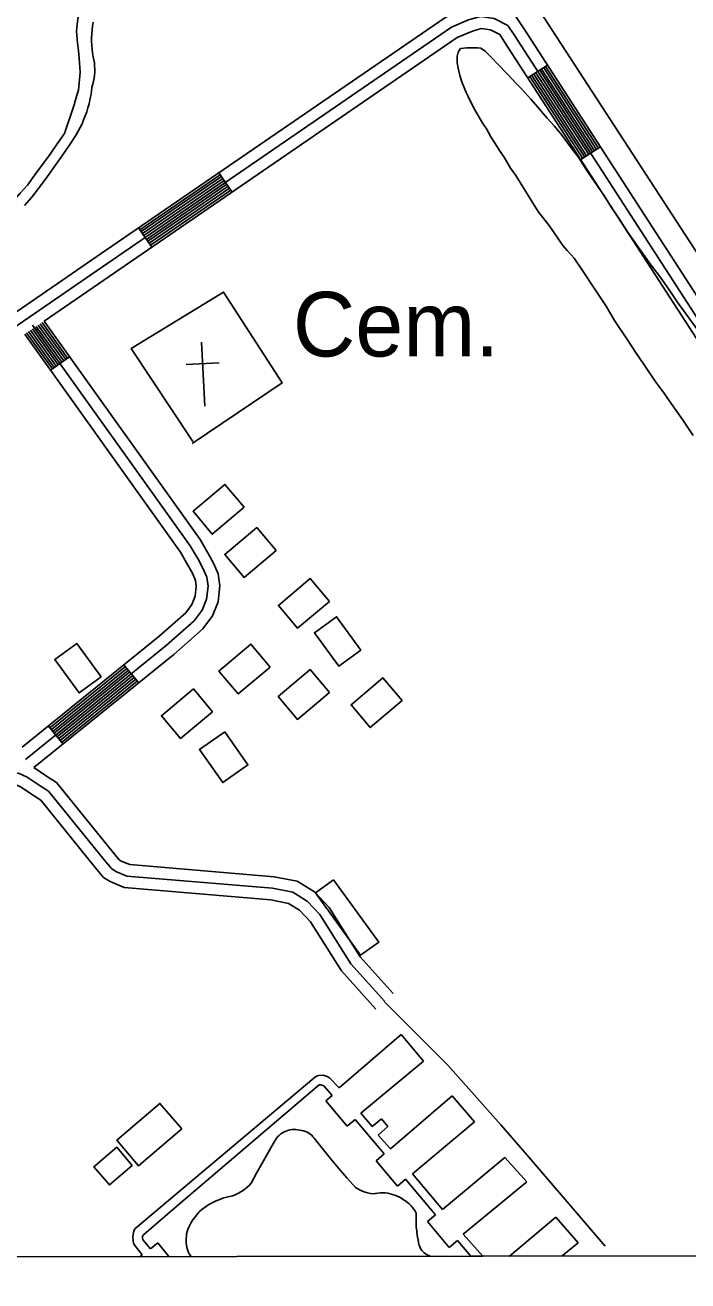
# Model space of a CAD drawing. Extents: x 3324104 to 3361979, y 612876 to 638273.
# Drawn here: x 3345889 to 3346740, y 618257 to 619871 of the extents above; entities that cross this region are included whole.
import ezdxf

# ---------------------------------------------------------------- set-up
doc = ezdxf.new("R2010")
doc.units = 0
for name, color, linetype in [('V-BLDG-OTLN', 7, 'Continuous'), ('V-GRID-FRAM', 7, 'Continuous'), ('V-ROAD-CNTR', 7, 'Continuous'), ('V-SITE-OTLN', 7, 'Continuous'), ('V-SITE-OTLN-IDEN', 7, 'Continuous'), ('V-SITE-VEGE', 7, 'Continuous'), ('V-TOPO-SHOR', 7, 'Continuous')]:
    doc.layers.add(name, color=color, linetype=linetype)

msp = doc.modelspace()

# ---------------------------------------------------------------- linework, layer by layer
at = {"layer": 'V-BLDG-OTLN'}
for p, q in [((3346292.4, 618504.9), (3346372.1, 618573.4)), ((3346372.1, 618573.4), (3346400.5, 618539.2)), ((3346400.5, 618539.2), (3346320.3, 618472.3)), ((3346029.9, 618323.9), (3346259.8, 618517.6)), ((3346259.8, 618517.6), (3346263.1, 618520)), ((3346263.1, 618520), (3346264.4, 618520.4)), ((3346266.8, 618508.8), (3346263.9, 618506.8)), ((3346264.4, 618520.4), (3346266.1, 618520.8)), ((3346266.1, 618520.8), (3346271.9, 618521.2)), ((3346268.9, 618508.8), (3346266.8, 618508.8)), ((3346272.8, 618507.5), (3346268.9, 618508.8)), ((3346271.9, 618521.2), (3346273.1, 618520.8)), ((3346273.1, 618520.8), (3346276.8, 618519.5)), ((3346276.8, 618519.5), (3346279.7, 618517.8)), ((3346279.7, 618517.8), (3346292.4, 618504.9)), ((3346263.9, 618506.8), (3346081.1, 618350.8)), ((3346283.2, 618495.2), (3346272.8, 618507.5)), ((3346275.1, 618488.4), (3346283.2, 618495.2)), ((3346358.1, 618426.8), (3346437.4, 618494.6)), ((3346437.4, 618494.6), (3346466.1, 618461.2)), ((3346302.6, 618455.7), (3346275.1, 618488.4)), ((3346312.8, 618464.3), (3346302.6, 618455.7)), ((3346350.1, 618420), (3346312.8, 618464.3)), ((3346320.3, 618472.3), (3346334.7, 618455.2)), ((3346334.7, 618455.2), (3346346.8, 618465.1)), ((3346346.8, 618465.1), (3346355, 618455.5)), ((3346466.1, 618461.2), (3346386.4, 618394.7)), ((3346355, 618455.5), (3346342.5, 618444.4)), ((3346342.5, 618444.4), (3346358.1, 618426.8)), ((3346339.7, 618411.2), (3346350.1, 618420)), ((3346425, 618348.8), (3346505.1, 618415.7)), ((3346505.1, 618415.7), (3346533.4, 618384.4)), ((3346367.1, 618378.7), (3346339.7, 618411.2)), ((3346377.7, 618387.6), (3346367.1, 618378.7)), ((3346416.1, 618342), (3346377.7, 618387.6)), ((3346386.4, 618394.7), (3346425, 618348.8)), ((3346533.4, 618384.4), (3346451.7, 618317.1)), ((3346081.1, 618350.8), (3346041, 618316.3)), ((3346405.6, 618333.2), (3346416.1, 618342)), ((3346433.7, 618299.8), (3346405.6, 618333.2)), ((3346511.1, 618288.9), (3346570.8, 618338.9)), ((3346570.8, 618338.9), (3346599.5, 618305.9)), ((3346027.3, 618313.9), (3346027.8, 618316.4)), ((3346027.8, 618316.4), (3346028.6, 618321)), ((3346028.6, 618321), (3346029.9, 618323.9)), ((3346041, 618316.3), (3346039.8, 618314.3)), ((3346451.7, 618317.1), (3346476.9, 618288.8)), ((3346027.7, 618308.1), (3346027.3, 618313.9)), ((3346028.5, 618304), (3346027.7, 618308.1)), ((3346039.2, 618290.6), (3346028.5, 618304)), ((3346039.8, 618314.3), (3346039.8, 618312.2)), ((3346039.8, 618312.2), (3346040.1, 618309.7)), ((3346040.1, 618309.7), (3346050, 618298)), ((3346050, 618298), (3346059.2, 618305.8)), ((3346059.2, 618305.8), (3346073.5, 618288.1)), ((3346444.4, 618308.8), (3346433.7, 618299.8)), ((3346461.3, 618288.8), (3346444.4, 618308.8)), ((3346599.5, 618305.9), (3346578.9, 618289)), ((3346036.2, 618288), (3346039.2, 618290.6)), ((3346073.5, 618288.1), (3346036.2, 618288)), ((3346476.9, 618288.8), (3346461.3, 618288.8)), ((3346578.9, 618289), (3346511.1, 618288.9))]:
    msp.add_line(p, q, dxfattribs=at)
for points in [[(3346170.3, 619251.1), (3346129.3, 619216.5), (3346104.6, 619245.9), (3346145.6, 619280.4)], [(3346211.2, 619195.6), (3346170.2, 619161), (3346145.4, 619190.4), (3346186.4, 619224.9)], [(3346280, 619130.2), (3346239, 619095.6), (3346214.3, 619125), (3346255.2, 619159.5)], [(3346320.2, 619067.6), (3346289, 619110.5), (3346260.6, 619089.9), (3346291.8, 619047)], [(3345986.6, 619033.2), (3345955.4, 619076.1), (3345927, 619055.5), (3345958.2, 619012.5)], [(3346203.7, 619045.8), (3346162.7, 619011.3), (3346137.9, 619040.6), (3346178.9, 619075.2)], [(3346279.7, 619013), (3346238.7, 618978.5), (3346214, 619007.8), (3346255, 619042.4)], [(3346373.3, 619002.6), (3346332.3, 618968), (3346307.6, 618997.4), (3346348.6, 619031.9)], [(3346129.7, 618988.3), (3346088.7, 618953.8), (3346064, 618983.1), (3346105, 619017.7)], [(3346145.3, 618962.4), (3346175.2, 618920.1), (3346142.8, 618897.2), (3346112.9, 618939.6)], [(3346285, 618772.2), (3346343.1, 618692.1), (3346319.9, 618675.3), (3346261.8, 618755.4)], [(3346090.1, 618452.3), (3346034.7, 618404.9), (3346006.7, 618437.7), (3346062.1, 618485)], [(3346026.5, 618405.3), (3345997.1, 618380.3), (3345977.3, 618403.7), (3346006.8, 618428.6)]]:
    msp.add_lwpolyline(points, close=True, dxfattribs=at)
at = {"layer": 'V-GRID-FRAM'}
msp.add_lwpolyline([(3328194.1, 636440.7), (3359767.9, 636495.9), (3359807.6, 618312.1), (3328217.9, 618256.9), (3328194.1, 636440.7)], dxfattribs=at)
at = {"layer": 'V-ROAD-CNTR'}
for p, q in [((3346560, 619819.2), (3346534.8, 619802.9)), ((3346627.9, 619714.2), (3346602.7, 619697.9)), ((3346137.8, 619681), (3346154.7, 619656.2)), ((3346034.7, 619610.2), (3346051.7, 619585.5)), ((3345921.5, 619427.1), (3345945.9, 619444.6)), ((3346015.9, 619048.7), (3346034.8, 619025.4)), ((3345918.8, 618970), (3345937.7, 618946.7))]:
    msp.add_line(p, q, dxfattribs=at)
for points in [[(3345993.5, 619582), (3346429.4, 619881.1), (3346453.3, 619891.4), (3346463, 619894.3)], [(3346001.9, 619569.6), (3346436.7, 619867.9), (3346458.4, 619877.3), (3346473.9, 619881.8), (3346491.6, 619879), (3346509, 619870.2), (3346517, 619858), (3346870.8, 619310.8), (3347256.8, 618710.3), (3347528.8, 618293.7)], [(3346497.5, 619892.8), (3346519.3, 619881.8), (3346529.6, 619866.2), (3346883.4, 619319), (3347269.3, 618718.5), (3347546.7, 618293.7)], [(3346010.4, 619557.2), (3346444, 619854.7), (3346463.4, 619863.1), (3346474.9, 619866.4), (3346486.9, 619864.5), (3346498.7, 619858.6), (3346504.4, 619849.8), (3346858.2, 619302.7), (3347244.2, 618702.1), (3347510.9, 618293.7)], [(3346555, 619815.9), (3346622.8, 619710.9)], [(3346557.5, 619817.5), (3346625.4, 619712.6)], [(3346537.3, 619804.5), (3346605.2, 619699.5)], [(3346539.8, 619806.1), (3346607.7, 619701.2)], [(3346542.4, 619807.7), (3346610.2, 619702.8)], [(3346544.9, 619809.4), (3346612.8, 619704.4)], [(3346547.4, 619811), (3346615.3, 619706)], [(3346549.9, 619812.6), (3346617.8, 619707.7)], [(3346552.4, 619814.3), (3346620.3, 619709.3)], [(3346036.4, 619607.8), (3346139.5, 619678.5)], [(3346038.1, 619605.3), (3346141.2, 619676)], [(3346039.8, 619602.8), (3346142.9, 619673.5)], [(3346041.5, 619600.3), (3346144.5, 619671.1)], [(3346043.2, 619597.9), (3346146.2, 619668.6)], [(3346044.9, 619595.4), (3346147.9, 619666.1)], [(3346046.6, 619592.9), (3346149.6, 619663.6)], [(3346048.3, 619590.5), (3346151.3, 619661.2)], [(3346050, 619588), (3346153, 619658.7)], [(3345993.5, 619581.9), (3345814.1, 619458.6)], [(3346001.9, 619569.6), (3345486, 619214.9), (3345479.6, 619206.5), (3345476.2, 619197), (3345476.1, 619184.6), (3345489.7, 619161), (3345735.1, 618800.2)], [(3346010.4, 619557.2), (3345913.2, 619490.4)], [(3345889.4, 618926.9), (3346070.1, 619073.4), (3346106.2, 619105.2), (3346116.5, 619118.9), (3346122, 619133.1), (3346123.9, 619149.9), (3346122.2, 619161.2), (3346117.3, 619172.8), (3346111, 619184.2), (3346101.1, 619201.4), (3345898.6, 619485)], [(3345926.4, 619430.6), (3345893.4, 619476.8)], [(3345928.8, 619432.3), (3345895.9, 619478.5)], [(3345931.3, 619434.1), (3345898.4, 619480.2)], [(3345900.3, 618916.5), (3346079.8, 619062), (3346117.3, 619094.9), (3346129.7, 619111.6), (3346136.7, 619129.4), (3346139.1, 619150.2), (3346136.7, 619165.4), (3346130.8, 619179.3), (3346124.1, 619191.5), (3346113.7, 619209.5), (3345913.2, 619490.4)], [(3345933.7, 619435.8), (3345900.8, 619481.9)], [(3345936.1, 619437.6), (3345903.3, 619483.6)], [(3345938.6, 619439.3), (3345905.8, 619485.3)], [(3345941, 619441.1), (3345908.2, 619487)], [(3345910.7, 619488.7), (3345943.5, 619442.8)], [(3345885.2, 618942.8), (3346060.5, 619084.9), (3346095.2, 619115.4), (3346103.2, 619126.3), (3346107.3, 619136.7), (3346108.8, 619149.6), (3346107.7, 619157.1), (3346103.8, 619166.2), (3346097.9, 619176.9), (3346088.5, 619193.3), (3345888.5, 619473.4)], [(3345923.9, 619428.9), (3345890.9, 619475.1)], [(3345920.7, 618967.7), (3346017.8, 619046.4)], [(3345922.6, 618965.4), (3346019.7, 619044.1)], [(3345924.4, 618963), (3346021.5, 619041.7)], [(3345926.3, 618960.7), (3346023.4, 619039.4)], [(3345928.2, 618958.4), (3346025.3, 619037.1)], [(3345930.1, 618956), (3346027.2, 619034.8)], [(3345932, 618953.7), (3346029.1, 619032.4)], [(3345933.9, 618951.4), (3346031, 619030.1)], [(3345935.8, 618949), (3346032.9, 619027.8)], [(3345900.3, 618916.5), (3345916.4, 618905.7), (3345929.2, 618897.4), (3346001.9, 618807.5), (3346009.8, 618798.2), (3346012.4, 618796.5), (3346023.4, 618791.9), (3346208.8, 618776.3), (3346238.5, 618770.5), (3346260.5, 618756.9), (3346279.5, 618736.9), (3346319.4, 618673.5), (3346361.7, 618626.3)], [(3345245.2, 618289.7), (3345223.2, 618321.1), (3345211.1, 618339.1), (3345210.6, 618354.2), (3345220.7, 618367.6), (3345590.3, 618679.3), (3345766.4, 618826.3), (3345857.1, 618903.9), (3345868.3, 618908.9), (3345880.2, 618909.6), (3345891.4, 618904.4), (3345908.1, 618893.2), (3345919, 618886.1), (3345990.4, 618797.9), (3345999.8, 618786.9), (3346005.3, 618783.2), (3346019.7, 618777.2), (3346206.7, 618761.4), (3346232.9, 618756.3), (3346251, 618745.1), (3346267.6, 618727.7), (3346307.4, 618664.4), (3346350.5, 618616.3)], [(3345550.2, 618625.9), (3345599.9, 618667.8), (3345776, 618814.8), (3345865.3, 618891.1), (3345871.9, 618894.1), (3345877.3, 618894.4), (3345884, 618891.3), (3345899.8, 618880.7), (3345908.9, 618874.8), (3345978.8, 618788.3), (3345989.7, 618775.5), (3345998.2, 618770), (3346016.1, 618762.4), (3346204.7, 618746.5), (3346227.4, 618742.1), (3346241.5, 618733.4), (3346255.7, 618718.4), (3346295.4, 618655.3), (3346339.3, 618606.3)], [(3346350.1, 618616.1), (3346431.8, 618534.3), (3346465.9, 618495.9), (3346499.9, 618457.3), (3346533.7, 618418.5), (3346567.3, 618379.7), (3346600.8, 618340.7), (3346634.1, 618301.5)], [(3346174, 618377.3), (3346176.7, 618379.7), (3346179.1, 618382.4), (3346186.1, 618395.4), (3346193.2, 618408.3), (3346200.5, 618421.1), (3346208, 618433.8), (3346209.1, 618436.1), (3346210.4, 618438.3), (3346211.9, 618440.3), (3346213.6, 618442.3), (3346215.5, 618444.1), (3346217.4, 618445.7), (3346219.6, 618447.1), (3346221.8, 618448.4), (3346224.1, 618449.4), (3346226.5, 618450.3), (3346229, 618450.9), (3346231.6, 618451.3), (3346234.1, 618451.5), (3346236.7, 618451.5), (3346239.2, 618451.2), (3346241.7, 618450.8), (3346244.2, 618450.1), (3346246.6, 618449.6), (3346248.9, 618448.9), (3346251.1, 618448), (3346253.2, 618446.9), (3346255.1, 618445.5), (3346257, 618444), (3346258.6, 618442.2), (3346260.1, 618440.3), (3346270.3, 618427.3), (3346280.8, 618414.5), (3346291.4, 618401.9), (3346302.3, 618389.4), (3346313.4, 618377.1), (3346316.3, 618375.2), (3346319.3, 618373.6), (3346322.4, 618372.1), (3346325.7, 618370.9), (3346329, 618369.9), (3346332.4, 618369.1), (3346335.8, 618368.6), (3346338.9, 618369.3), (3346342.1, 618369.8), (3346345.2, 618370), (3346348.4, 618370), (3346351.6, 618369.9), (3346354.7, 618369.5), (3346357.8, 618368.9), (3346360.9, 618368.1), (3346363.9, 618367.2), (3346366.9, 618366), (3346369.7, 618364.6), (3346372.5, 618363.1), (3346375.1, 618361.3), (3346377.6, 618359.7), (3346380, 618357.8), (3346382.3, 618355.8), (3346384.4, 618353.7), (3346386.4, 618351.4), (3346388.2, 618349), (3346389.9, 618346.5), (3346391.4, 618343.9), (3346391.1, 618338.2), (3346391.1, 618332.4), (3346391.4, 618326.6), (3346391.9, 618320.9), (3346392.6, 618315.2), (3346393.6, 618309.5), (3346394.8, 618303.9), (3346395.4, 618301.8), (3346396.3, 618299.8), (3346397.4, 618297.8), (3346398.7, 618296), (3346400.1, 618294.4), (3346401.7, 618292.9), (3346403.4, 618291.6), (3346405.3, 618290.4), (3346407.3, 618289.5), (3346409.4, 618288.7), (3346409.5, 618288.7)], [(3346097.5, 618297.1), (3346096.7, 618299.9), (3346096.2, 618302.8), (3346095.8, 618305.7), (3346095.6, 618308.6), (3346095.7, 618311.6), (3346096, 618314.5), (3346096.4, 618317.4), (3346097.1, 618320.3), (3346098, 618323.1), (3346099, 618325.8), (3346100.3, 618328.4), (3346101.7, 618331), (3346103.7, 618334.2), (3346105.8, 618337.3), (3346108.1, 618340.3), (3346110.5, 618343.2), (3346113.1, 618345.9), (3346115.9, 618348.5), (3346118.8, 618350.9), (3346121.8, 618353.1), (3346124.9, 618355.1), (3346128.2, 618357), (3346133.4, 618359.4), (3346138.8, 618361.6), (3346144.2, 618363.5), (3346149.8, 618365.1), (3346155.4, 618366.4), (3346158.8, 618367.7), (3346162.1, 618369.2), (3346165.2, 618370.9), (3346168.3, 618372.8), (3346171.3, 618375), (3346174, 618377.3)], [(3346102.1, 618288.1), (3346099.7, 618291.6), (3346098.5, 618294.3), (3346097.5, 618297.1)]]:
    msp.add_lwpolyline(points, dxfattribs=at)
at = {"layer": 'V-SITE-OTLN'}
for p, q in [((3346119.7, 619381), (3346115.4, 619463.2)), ((3346138.1, 619436.9), (3346095.6, 619434.7))]:
    msp.add_line(p, q, dxfattribs=at)
msp.add_lwpolyline([(3346104.5, 619335.7), (3346025.2, 619455), (3346143.8, 619527.6), (3346219, 619410.8), (3346103.7, 619333.2)], dxfattribs=at)
at = {"layer": 'V-SITE-VEGE'}
for p, q in [((3346444, 619830.8), (3346445, 619835.9)), ((3346445, 619835.9), (3346448.2, 619840.6)), ((3346448.2, 619840.6), (3346456.2, 619841.4)), ((3346456.2, 619841.4), (3346470.1, 619841.5)), ((3346470.1, 619841.5), (3346474.4, 619840.9)), ((3346474.4, 619840.9), (3346479.9, 619837.3)), ((3346479.9, 619837.3), (3346489.4, 619827.9)), ((3346444, 619822.1), (3346444, 619830.8)), ((3346445.2, 619815.2), (3346444, 619822.1)), ((3346489.4, 619827.9), (3346494.9, 619821.8)), ((3346494.9, 619821.8), (3346509.6, 619806.6)), ((3346447.4, 619806.1), (3346445.2, 619815.2)), ((3346450, 619797.8), (3346447.4, 619806.1)), ((3346509.6, 619806.6), (3346519.5, 619795.8)), ((3346455.6, 619784), (3346450, 619797.8)), ((3346458.2, 619778.9), (3346455.6, 619784)), ((3346519.5, 619795.8), (3346526.8, 619788.2)), ((3346526.8, 619788.2), (3346538.6, 619775.6)), ((3346465.2, 619764.1), (3346458.2, 619778.9)), ((3346538.6, 619775.6), (3346547, 619765.8)), ((3346477, 619744.2), (3346465.2, 619764.1)), ((3346547, 619765.8), (3346559.5, 619751)), ((3346559.5, 619751), (3346568.3, 619741.3)), ((3346481.4, 619737.3), (3346477, 619744.2)), ((3346487, 619727.2), (3346481.4, 619737.3)), ((3346568.3, 619741.3), (3346577.5, 619730.4)), ((3346491.7, 619719.9), (3346487, 619727.2)), ((3346499.1, 619708.4), (3346491.7, 619719.9)), ((3346577.5, 619730.4), (3346590.3, 619713.1)), ((3346504.3, 619700.8), (3346499.1, 619708.4)), ((3346590.3, 619713.1), (3346599.1, 619701.5)), ((3346512.4, 619686.7), (3346504.3, 619700.8)), ((3346519.3, 619677.3), (3346512.4, 619686.7)), ((3346599.1, 619701.5), (3346611.3, 619682.4)), ((3346528.2, 619662.8), (3346519.3, 619677.3)), ((3346611.3, 619682.4), (3346633, 619650.9)), ((3346544.8, 619636), (3346528.2, 619662.8)), ((3346633, 619650.9), (3346641.4, 619637.5)), ((3346548.8, 619629.9), (3346544.8, 619636)), ((3346562, 619613.3), (3346548.8, 619629.9)), ((3346641.4, 619637.5), (3346653.6, 619619.1)), ((3346579.7, 619587.6), (3346562, 619613.3)), ((3346653.6, 619619.1), (3346661.7, 619606.4)), ((3346661.7, 619606.4), (3346671.6, 619592)), ((3346671.6, 619592), (3346692.6, 619562.7)), ((3346585.2, 619581.1), (3346579.7, 619587.6)), ((3346590.3, 619575.7), (3346585.2, 619581.1)), ((3346594, 619571), (3346590.3, 619575.7)), ((3346606.5, 619552.9), (3346594, 619571)), ((3346692.6, 619562.7), (3346704, 619547.5)), ((3346617.5, 619536.6), (3346606.5, 619552.9)), ((3346704, 619547.5), (3346715.4, 619531.6)), ((3346635.2, 619509.5), (3346617.5, 619536.6)), ((3346715.4, 619531.6), (3346726.4, 619515.3)), ((3346645.9, 619491.1), (3346635.2, 619509.5)), ((3346726.4, 619515.3), (3346753.2, 619478.8)), ((3346662.8, 619466.1), (3346645.9, 619491.1)), ((3346673.1, 619450.2), (3346662.8, 619466.1)), ((3346684.1, 619434.3), (3346673.1, 619450.2)), ((3346699.2, 619411.9), (3346684.1, 619434.3)), ((3346709.2, 619398.1), (3346699.2, 619411.9)), ((3346718.7, 619384.4), (3346709.2, 619398.1)), ((3346733.4, 619363.8), (3346718.7, 619384.4)), ((3346747, 619343.2), (3346733.4, 619363.8))]:
    msp.add_line(p, q, dxfattribs=at)
at = {"layer": 'V-TOPO-SHOR'}
for p, q in [((3346426.4, 620079.5), (3347579.9, 618301.3)), ((3345939.4, 619731.6), (3345951.9, 619768.3))]:
    msp.add_line(p, q, dxfattribs=at)
for points in [[(3345951.9, 619768.3), (3345955.3, 619780.7), (3345957.4, 619787.3), (3345959.5, 619810.1), (3345958.9, 619822.2), (3345957.3, 619838.2), (3345956.4, 619847.3), (3345955, 619863.1), (3345956.1, 619875.6), (3345958.8, 619889.7), (3345959.8, 619894.5)], [(3345888.3, 619639.1), (3345897.7, 619649.6), (3345907.5, 619662.6), (3345917.2, 619675.7), (3345926.8, 619689), (3345936.1, 619702.4), (3345945.3, 619715.9), (3345954.3, 619729.5), (3345957, 619734.2), (3345959.6, 619739), (3345962, 619743.9), (3345964.1, 619748.9), (3345966.2, 619754), (3345968, 619759.1), (3345969.6, 619764.3), (3345971, 619769.5), (3345972.2, 619774.8), (3345973.3, 619780.1), (3345974.1, 619785.5), (3345974.7, 619790.9), (3345975.9, 619794.7), (3345976.8, 619798.6), (3345977.5, 619802.5), (3345978, 619806.4), (3345978.3, 619810.4), (3345978.4, 619814.3), (3345978.2, 619818.3), (3345977.9, 619822.3), (3345977.3, 619826.2), (3345976.4, 619830.1), (3345975.6, 619835), (3345975, 619839.9), (3345974.6, 619844.8), (3345974.3, 619849.7), (3345974.3, 619854.7), (3345974.6, 619859.6), (3345975, 619864.5), (3345975.6, 619869.4), (3345976.4, 619874.3)], [(3345782, 619498.9), (3345780.2, 619499.6), (3345777.3, 619502.1), (3345789.9, 619518.8), (3345807.5, 619549.5), (3345811.9, 619555.4), (3345816.2, 619561.5), (3345820.3, 619567.7), (3345824.2, 619574), (3345827.9, 619580.4), (3345831.5, 619587), (3345834.9, 619593.6), (3345838.1, 619600.3), (3345846.6, 619611.4), (3345855.3, 619622.5), (3345864.2, 619633.3), (3345873.2, 619644.1), (3345882.4, 619654.7), (3345891.8, 619665.2), (3345901.6, 619678.2), (3345911.3, 619691.4), (3345920.9, 619704.7), (3345930.2, 619718), (3345939.4, 619731.6)]]:
    msp.add_lwpolyline(points, dxfattribs=at)

# ---------------------------------------------------------------- texts
at = {"layer": 'V-SITE-OTLN-IDEN'}
msp.add_text('Cem.', height=83, dxfattribs=at).set_placement((3346232.8, 619444.9))

doc.saveas('drawing.dxf')
